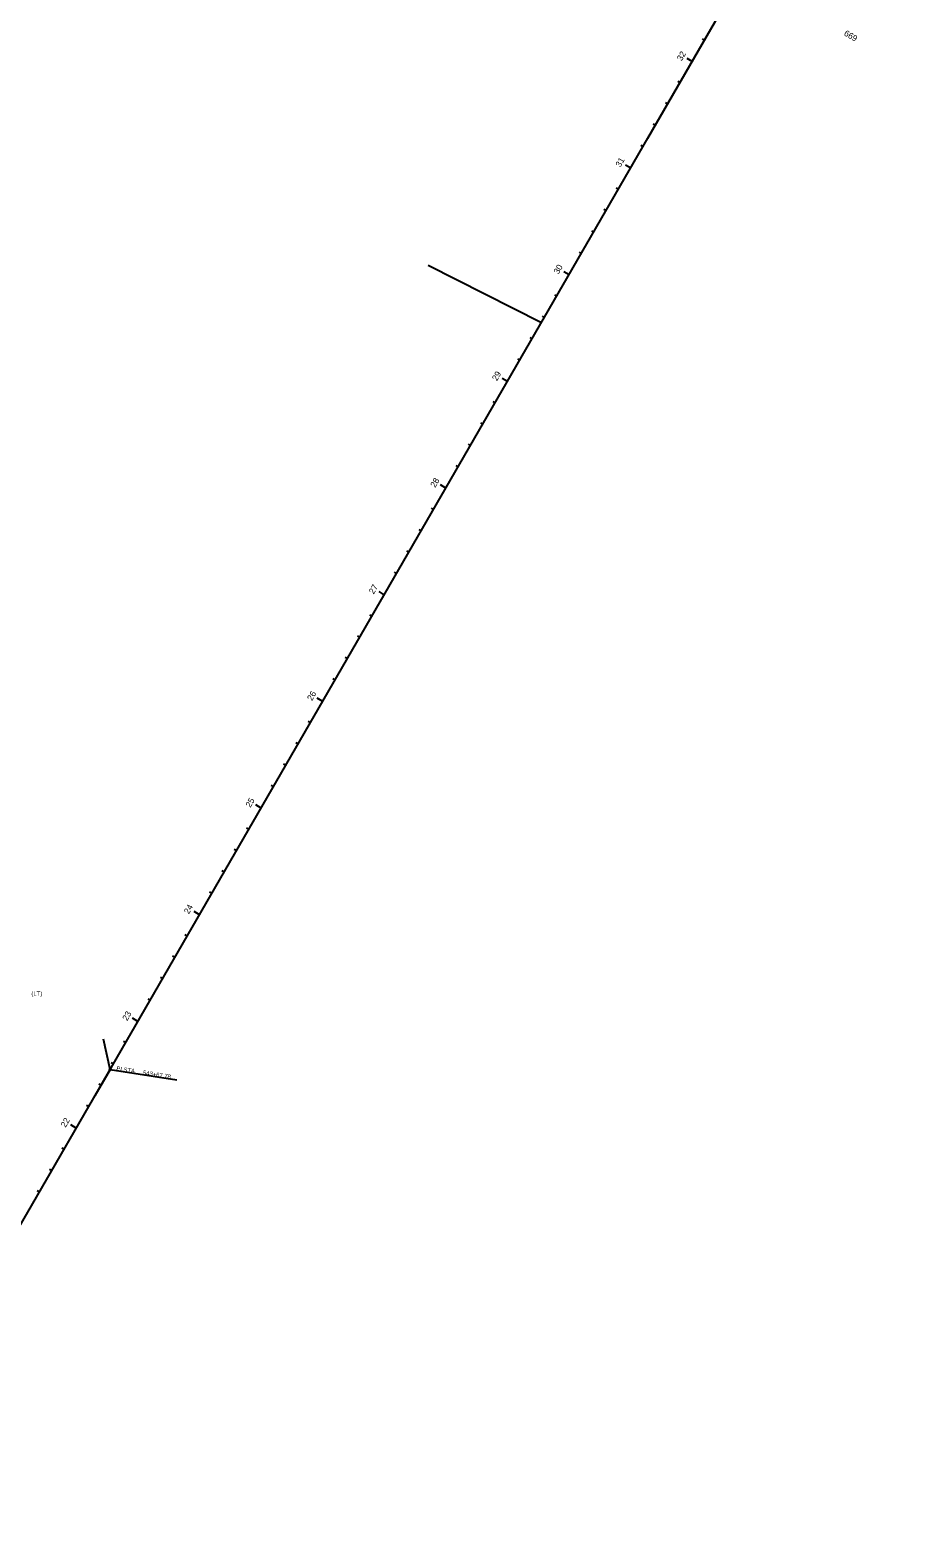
# Model space of a CAD drawing. Extents: x 2003883 to 2007688, y 399149 to 412300.
# Drawn here: x 2006250 to 2006969, y 401364 to 402588 of the extents above; entities that cross this region are included whole.
import ezdxf

# ---------------------------------------------------------------- set-up
doc = ezdxf.new("R2010")
doc.units = 0
for name, color, linetype in [('BaselineSurvey', 7, 'Continuous'), ('CLConst_dp', 7, 'Continuous'), ('TextAlgnCardinalPnt', 7, 'Continuous'), ('TextAlgnCurveData', 7, 'Continuous'), ('TextAlgnStation100', 7, 'Continuous'), ('TextAlgnStation1000', 7, 'Continuous'), ('TextAlgnStation500', 7, 'Continuous'), ('TextAlgnTicks100', 7, 'Continuous'), ('TextAlgnTicks1000', 7, 'Continuous'), ('TextAlgnTicks500', 7, 'Continuous'), ('TextAlgnTicks5000', 7, 'Continuous')]:
    doc.layers.add(name, color=color, linetype=linetype)

msp = doc.modelspace()

# ---------------------------------------------------------------- linework, layer by layer
at = {"layer": 'BaselineSurvey'}
msp.add_lwpolyline([(2006095.1, 401364.2), (2006751.4, 402500.6), (2007687.7, 404121.7)], dxfattribs=at)
at = {"layer": 'CLConst_dp'}
msp.add_line((2006664.9, 402350.8), (2006572.9, 402397.4), dxfattribs=at)
at = {"layer": 'TextAlgnCardinalPnt'}
for q in [(2006309.6, 401769.1), (2006302.3, 401723), (2006369.1, 401736)]:
    msp.add_line((2006314.8, 401744.6), q, dxfattribs=at)
msp.add_lwpolyline([(2006315.9, 401744.4), (2006314.4, 401745.7), (2006314.1, 401743.7)], close=True, dxfattribs=at)
at = {"layer": 'TextAlgnTicks100'}
for p, q in [((2006797.4, 402580.3), (2006795.7, 402581.3)), ((2006787.4, 402563), (2006783.1, 402565.5)), ((2006777.4, 402545.7), (2006775.7, 402546.7)), ((2006767.4, 402528.3), (2006765.7, 402529.3)), ((2006757.4, 402511), (2006755.7, 402512)), ((2006747.4, 402493.7), (2006745.7, 402494.7)), ((2006737.4, 402476.4), (2006733.1, 402478.9)), ((2006727.4, 402459.1), (2006725.7, 402460.1)), ((2006717.4, 402441.7), (2006715.7, 402442.7)), ((2006707.4, 402424.4), (2006705.7, 402425.4)), ((2006697.4, 402407.1), (2006695.7, 402408.1)), ((2006687.4, 402389.8), (2006683.1, 402392.3)), ((2006677.4, 402372.5), (2006675.7, 402373.5)), ((2006667.4, 402355.2), (2006665.7, 402356.2)), ((2006657.4, 402337.8), (2006655.7, 402338.8)), ((2006647.4, 402320.5), (2006645.7, 402321.5)), ((2006637.4, 402303.2), (2006633.1, 402305.7)), ((2006627.4, 402285.9), (2006625.7, 402286.9)), ((2006617.4, 402268.6), (2006615.7, 402269.6)), ((2006607.4, 402251.2), (2006605.7, 402252.2)), ((2006597.4, 402233.9), (2006595.7, 402234.9)), ((2006587.4, 402216.6), (2006583.1, 402219.1)), ((2006577.4, 402199.3), (2006575.7, 402200.3)), ((2006567.4, 402182), (2006565.7, 402183)), ((2006557.4, 402164.6), (2006555.7, 402165.6)), ((2006547.4, 402147.3), (2006545.7, 402148.3)), ((2006537.4, 402130), (2006533.1, 402132.5)), ((2006527.4, 402112.7), (2006525.6, 402113.7)), ((2006517.4, 402095.4), (2006515.6, 402096.4)), ((2006507.4, 402078.1), (2006505.6, 402079.1)), ((2006497.4, 402060.7), (2006495.6, 402061.7)), ((2006487.4, 402043.4), (2006483, 402045.9)), ((2006477.4, 402026.1), (2006475.6, 402027.1)), ((2006467.4, 402008.8), (2006465.6, 402009.8)), ((2006457.4, 401991.5), (2006455.6, 401992.5)), ((2006447.4, 401974.1), (2006445.6, 401975.1)), ((2006437.4, 401956.8), (2006433, 401959.3)), ((2006427.4, 401939.5), (2006425.6, 401940.5)), ((2006417.3, 401922.2), (2006415.6, 401923.2)), ((2006407.3, 401904.9), (2006405.6, 401905.9)), ((2006397.3, 401887.5), (2006395.6, 401888.5)), ((2006387.3, 401870.2), (2006383, 401872.7)), ((2006377.3, 401852.9), (2006375.6, 401853.9)), ((2006367.3, 401835.6), (2006365.6, 401836.6)), ((2006357.3, 401818.3), (2006355.6, 401819.3)), ((2006347.3, 401800.9), (2006345.6, 401801.9)), ((2006337.3, 401783.6), (2006333, 401786.1)), ((2006327.3, 401766.3), (2006325.6, 401767.3)), ((2006317.3, 401749), (2006315.6, 401750)), ((2006307.3, 401731.7), (2006305.6, 401732.7)), ((2006297.3, 401714.4), (2006295.6, 401715.4)), ((2006287.3, 401697), (2006283, 401699.5)), ((2006277.3, 401679.7), (2006275.6, 401680.7)), ((2006267.3, 401662.4), (2006265.6, 401663.4)), ((2006257.3, 401645.1), (2006255.6, 401646.1))]:
    msp.add_line(p, q, dxfattribs=at)
at = {"layer": 'TextAlgnTicks1000'}
for p, q in [((2006787.4, 402563), (2006785.7, 402564)), ((2006687.4, 402389.8), (2006683.1, 402392.3)), ((2006587.4, 402216.6), (2006585.7, 402217.6)), ((2006487.4, 402043.4), (2006485.6, 402044.4)), ((2006387.3, 401870.2), (2006385.6, 401871.2)), ((2006287.3, 401697), (2006285.6, 401698))]:
    msp.add_line(p, q, dxfattribs=at)
at = {"layer": 'TextAlgnTicks500'}
for p, q in [((2006787.4, 402563), (2006785.7, 402564)), ((2006737.4, 402476.4), (2006735.7, 402477.4)), ((2006687.4, 402389.8), (2006683.1, 402392.3)), ((2006637.4, 402303.2), (2006635.7, 402304.2)), ((2006587.4, 402216.6), (2006585.7, 402217.6)), ((2006537.4, 402130), (2006535.6, 402131)), ((2006487.4, 402043.4), (2006485.6, 402044.4)), ((2006437.4, 401956.8), (2006433, 401959.3)), ((2006387.3, 401870.2), (2006385.6, 401871.2)), ((2006337.3, 401783.6), (2006335.6, 401784.6)), ((2006287.3, 401697), (2006285.6, 401698))]:
    msp.add_line(p, q, dxfattribs=at)
at = {"layer": 'TextAlgnTicks5000'}
msp.add_line((2006687.4, 402389.8), (2006685.7, 402390.8), dxfattribs=at)

# ---------------------------------------------------------------- texts
at = {"layer": 'TextAlgnCardinalPnt'}
for s, p in [('PI STA. ', (2006319.7, 401743.8)), ('543+67.78', (2006341.3, 401740.4))]:
    msp.add_text(s, height=3.48, rotation=350.965, dxfattribs=at).set_placement(p)
at = {"layer": 'TextAlgnCurveData'}
msp.add_text(' (LT)', height=3.48, dxfattribs=at).set_placement((2006249.6, 401804.4))
at = {"layer": 'TextAlgnStation100'}
for s, rotation, p in [('699', 149.9911, (2006922.1, 402583.2)), ('32', 59.9911, (2006778.8, 402563)), ('31', 59.9911, (2006729, 402476.8)), ('30', 59.9911, (2006678.8, 402389.9)), ('29', 59.9911, (2006628.8, 402303.2)), ('28', 59.9911, (2006578.7, 402216.6)), ('27', 59.9911, (2006528.8, 402130.1)), ('26', 59.9911, (2006478.7, 402043.5)), ('25', 59.9911, (2006428.7, 401956.8)), ('24', 59.9911, (2006378.7, 401870.3)), ('23', 59.9911, (2006328.7, 401783.6)), ('22', 59.9911, (2006278.7, 401697))]:
    msp.add_text(s, height=4.98, rotation=rotation, dxfattribs=at).set_placement(p)
at = {"layer": 'TextAlgnStation1000'}
msp.add_text('30', height=4.98, rotation=59.9911, dxfattribs=at).set_placement((2006678.8, 402389.9))
at = {"layer": 'TextAlgnStation500'}
for s, p in [('30', (2006678.8, 402389.9)), ('25', (2006428.7, 401956.8))]:
    msp.add_text(s, height=4.98, rotation=59.9911, dxfattribs=at).set_placement(p)

doc.saveas('drawing.dxf')
